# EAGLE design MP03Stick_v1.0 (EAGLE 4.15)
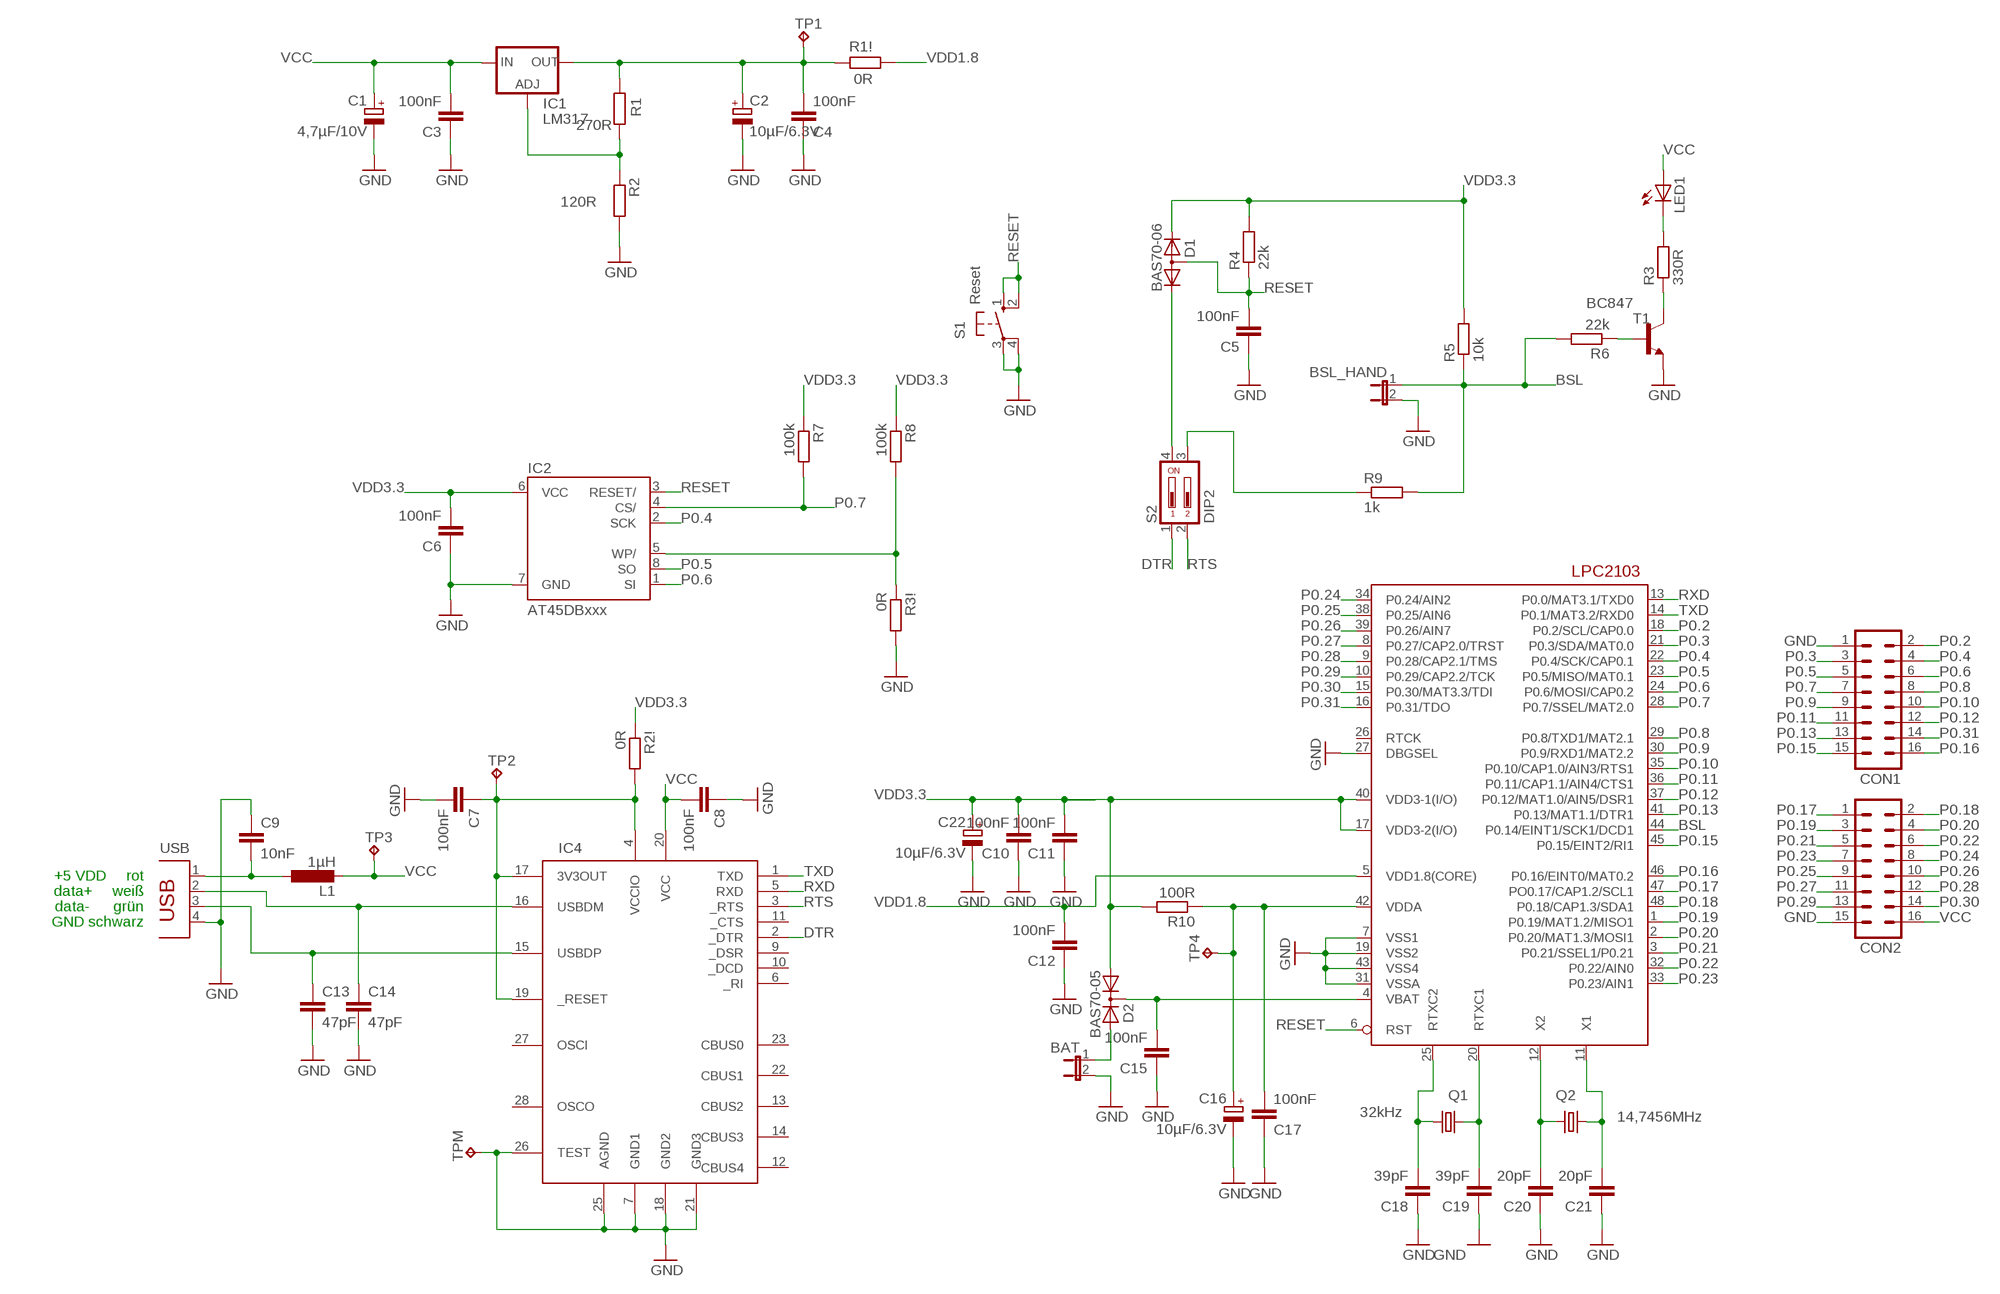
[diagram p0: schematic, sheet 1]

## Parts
BAT  JP1EMP  [JP1_MP]
BSL_HAND  JP1EMP  [JP1_MP]
C1  4,7µF/10V  CPOL-EUA/3216-18R  [A/3216-18R]
C2  10µF/6.3V  CPOL-EUA/3216-18R  [A/3216-18R]
C3  100nF  C-EUC0805K  [C0805K]
C4  100nF  C-EUC0805K  [C0805K]
C5  100nF  C-EUC0805K  [C0805K]
C6  100nF  C-EUC0805K  [C0805K]
C7  100nF  C-EUC0805K  [C0805K]
C8  100nF  C-EUC0805K  [C0805K]
C9  10nF  C-EUC0805K  [C0805K]
C10  100nF  C-EUC0805K  [C0805K]
C11  100nF  C-EUC0805K  [C0805K]
C12  100nF  C-EUC0805K  [C0805K]
C13  47pF  C-EUC0805K  [C0805K]
C14  47pF  C-EUC0805K  [C0805K]
C15  100nF  C-EUC0805K  [C0805K]
C16  10µF/6.3V  CPOL-EUA/3216-18R  [A/3216-18R]
C17  100nF  C-EUC0805K  [C0805K]
C18  39pF  C-EUC0805K  [C0805K]
C19  39pF  C-EUC0805K  [C0805K]
C20  20pF  C-EUC0805K  [C0805K]
C21  20pF  C-EUC0805K  [C0805K]
C22  10µF/6.3V  CPOL-EUA/3216-18R  [A/3216-18R]
CON1  ML16  [ML16]
CON2  ML16  [ML16]
D1  BAS70-06  [SOT23]
D2  BAS70-05  [SOT23]
IC1  LM317  LM317LSO8  [SO08]
IC2  AT45DBxxx  AT45DB  [SOIC8]
IC3  LPC2103  [LQFP48]
IC4  FT232RL  [SSOP28DB]
L1  1µH  L-EUL2825P  [L2825P]
LED1  LED3MM  [LED3MM]
Q1  32kHz  CRYTALTC26H  [TC26H]
Q2  14,7456MHz  CRYTALHC49U-V  [HC49U-V]
R1  270R  R-EU_R0805  [R0805]
R1!  0R  R-EU_R0805  [R0805]
R2  120R  R-EU_R0805  [R0805]
R2!  0R  R-EU_R0805  [R0805]
R3  330R  R-EU_R0805  [R0805]
R3!  0R  R-EU_R0805  [R0805]
R4  22k  R-EU_R0805  [R0805]
R5  10k  R-EU_R0805  [R0805]
R6  22k  R-EU_R0805  [R0805]
R7  100k  R-EU_R0805  [R0805]
R8  100k  R-EU_R0805  [R0805]
R9  1k  R-EU_R0805  [R0805]
R10  100R  R-EU_R0805  [R0805]
S1  Reset  10-XX  [B3F-10XX]
S2  DIP2  DS02  [DS-02]
T1  BC847  BC847-NPN-SOT23-BEC  [SOT23-BEC]
TP1  TP09SQ  [TP09SQ]
TP2  TP09SQ  [TP09SQ]
TP3  TP09SQ  [TP09SQ]
TP4  TP09SQ  [TP09SQ]
TPM  TP09SQ  [TP09SQ]
USB  PN61729  [PN61729]

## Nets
BSL: BSL_HAND.1 IC3.44(P0.14/EINT1/SCK1/DCD1) R5.1 R6.2 R9.2
DTR: IC4.2(_DTR) S2.1
GND: BAT.2 BSL_HAND.2 C1.- C2.- C3.1 C4.1 C5.1 C6.1 C7.2 C8.1 C9.1 C10.1 C11.1 C12.1 C13.2 C14.2 C15.1 C16.- C17.1 C18.1 C19.1 C20.1 C21.1 C22.- CON1.1 CON2.15 IC2.7(GND) IC3.7(VSS1) IC3.19(VSS2) IC3.27(DBGSEL) IC3.31(VSSA) IC3.43(VSS4) IC4.7(GND1) IC4.18(GND2) IC4.21(GND3) IC4.25(AGND) IC4.26(TEST) R2.2 R3!.2 S1.3(P) S1.4(P1) T1.E TPM.TP USB.4
N$1: C9.2 L1.1 USB.1
N$2: R6.1 T1.B
N$3: R9.1 S2.3
N$4: C14.1 IC4.16(USBDM) USB.2
N$5: R3.1 T1.C
N$6: LED1.K(C) R3.2
N$7: C13.1 IC4.15(USBDP) USB.3
N$8: D1.1(K1) S2.4
N$9: IC1.4(ADJ) R1.1 R2.1
N$10: BAT.1 D2.2(A2)
N$13: C19.2 IC3.20(RTXC1) Q1.2
N$14: C20.2 IC3.12(X2) Q2.2
N$15: C21.2 IC3.11(X1) Q2.1
N$16: C18.2 IC3.25(RTXC2) Q1.1
P0.2: CON1.2 IC3.18(P0.2/SCL/CAP0.0)
P0.3: CON1.3 IC3.21(P0.3/SDA/MAT0.0)
P0.4: CON1.4 IC2.2(SCK) IC3.22(P0.4/SCK/CAP0.1)
P0.5: CON1.5 IC2.8(SO) IC3.23(P0.5/MISO/MAT0.1)
P0.6: CON1.6 IC2.1(SI) IC3.24(P0.6/MOSI/CAP0.2)
P0.7: CON1.7 IC2.4(CS/) IC3.28(P0.7/SSEL/MAT2.0) R7.2
P0.8: CON1.8 IC3.29(P0.8/TXD1/MAT2.1)
P0.9: CON1.9 IC3.30(P0.9/RXD1/MAT2.2)
P0.10: CON1.10 IC3.35(P0.10/CAP1.0/AIN3/RTS1)
P0.11: CON1.11 IC3.36(P0.11/CAP1.1/AIN4/CTS1)
P0.12: CON1.12 IC3.37(P0.12/MAT1.0/AIN5/DSR1)
P0.13: CON1.13 IC3.41(P0.13/MAT1.1/DTR1)
P0.15: CON1.15 IC3.45(P0.15/EINT2/RI1)
P0.16: CON1.16 IC3.46(P0.16/EINT0/MAT0.2)
P0.17: CON2.1 IC3.47(PO0.17/CAP1.2/SCL1)
P0.18: CON2.2 IC3.48(P0.18/CAP1.3/SDA1)
P0.19: CON2.3 IC3.1(P0.19/MAT1.2/MISO1)
P0.20: CON2.4 IC3.2(P0.20/MAT1.3/MOSI1)
P0.21: CON2.5 IC3.3(P0.21/SSEL1/P0.21)
P0.22: CON2.6 IC3.32(P0.22/AIN0)
P0.23: CON2.7 IC3.33(P0.23/AIN1)
P0.24: CON2.8 IC3.34(P0.24/AIN2)
P0.25: CON2.9 IC3.38(P0.25/AIN6)
P0.26: CON2.10 IC3.39(P0.26/AIN7)
P0.27: CON2.11 IC3.8(P0.27/CAP2.0/TRST)
P0.28: CON2.12 IC3.9(P0.28/CAP2.1/TMS)
P0.29: CON2.13 IC3.10(P0.29/CAP2.2/TCK)
P0.30: CON2.14 IC3.15(P0.30/MAT3.3/TDI)
P0.31: CON1.14 IC3.16(P0.31/TDO)
RESET: C5.2 D1.3(A) IC2.3(RESET/) IC3.6(RST) R4.1 S1.1(S) S1.2(S1)
RTS: IC4.3(_RTS) S2.2
RXD: IC3.13(P0.0/MAT3.1/TXD0) IC4.5(RXD)
TXD: IC3.14(P0.1/MAT3.2/RXD0) IC4.1(TXD)
VBAT: C15.2 D2.3(C) IC3.4(VBAT)
VCC: C1.+ C3.2 C8.2 CON2.16 IC1.1(IN) IC4.20(VCC) L1.2 LED1.A TP3.TP
VDD1.8: C12.2 IC3.5(VDD1.8(CORE)) R1!.1
VDD1.8_OUT: C2.+ C4.2 IC1.7(OUT) R1!.2 R1.2 TP1.TP
VDD3.3: C6.2 C10.2 C11.2 C22.+ D1.2(K2) D2.1(A1) IC2.6(VCC) IC3.17(VDD3-2(I/O)) IC3.40(VDD3-1(I/O)) R2!.1 R4.2 R5.2 R7.1 R8.1 R10.2
VDDA: C16.+ C17.2 IC3.42(VDDA) R10.1 TP4.TP
VDDIO: C7.1 IC4.4(VCCIO) IC4.17(3V3OUT) IC4.19(_RESET) R2!.2 TP2.TP
WP/: IC2.5(WP/) R3!.1 R8.2
Unconnected: IC3.26(RTCK) IC4.6(_RI) IC4.9(_DSR) IC4.10(_DCD) IC4.11(_CTS) IC4.12(CBUS4) IC4.13(CBUS2) IC4.14(CBUS3) IC4.22(CBUS1) IC4.23(CBUS0) IC4.27(OSCI) IC4.28(OSCO)

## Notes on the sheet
- +5 VDD     rot
- data+     weiß
- data-      grün
- GND schwarz

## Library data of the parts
BAT BSL_HAND = jumper:JP1E: JUMPER
C1 C2 C16 C22 = rcl:CPOL-EU: POLARIZED CAPACITOR, European symbol
C3-C15 C17-C21 = rcl:C-EU: CAPACITOR, European symbol
CON1 CON2 = con-harting-ml:ML16: HARTING
D1 = diode_Mario:BAS70-06: Silicon Schottky Diodes General-purpose diode for high-speed switching
D2 = diode:BAS70-05: Silicon Schottky Diodes General-purpose diode for high-speed switching
IC1 = v-reg_Mario:LM317L: VOLTAGE REGULATOR
IC2 = atmel:AT45DB*
IC3 = philips-4:LPC2103: LPC2101/2102/2103 microcontroler from Philips
IC4 = ftdichip:FT232RL: USB UART 4th Generation USB UART (USB <-> Serial) Controller
L1 = rcl:L-EU: INDUCTOR, European symbol
LED1 = led:LED: LED
Q1 Q2 = crystal:CRYTAL: CRYSTAL
R1 R1! R2 R2! R3 R3! R4-R10 = rcl:R-EU_: RESISTOR, European symbol
S1 = switch-omron:10-XX: OMRON SWITCH
S2 = switch-dil:DS02: DIL/CODE SWITCH
T1 = transistor:*-NPN-: NPN Transistror
TP1-TP4 TPM = testpad:TP09SQ: TEST PIN
USB = con-berg:PN61729: BERG USB connector

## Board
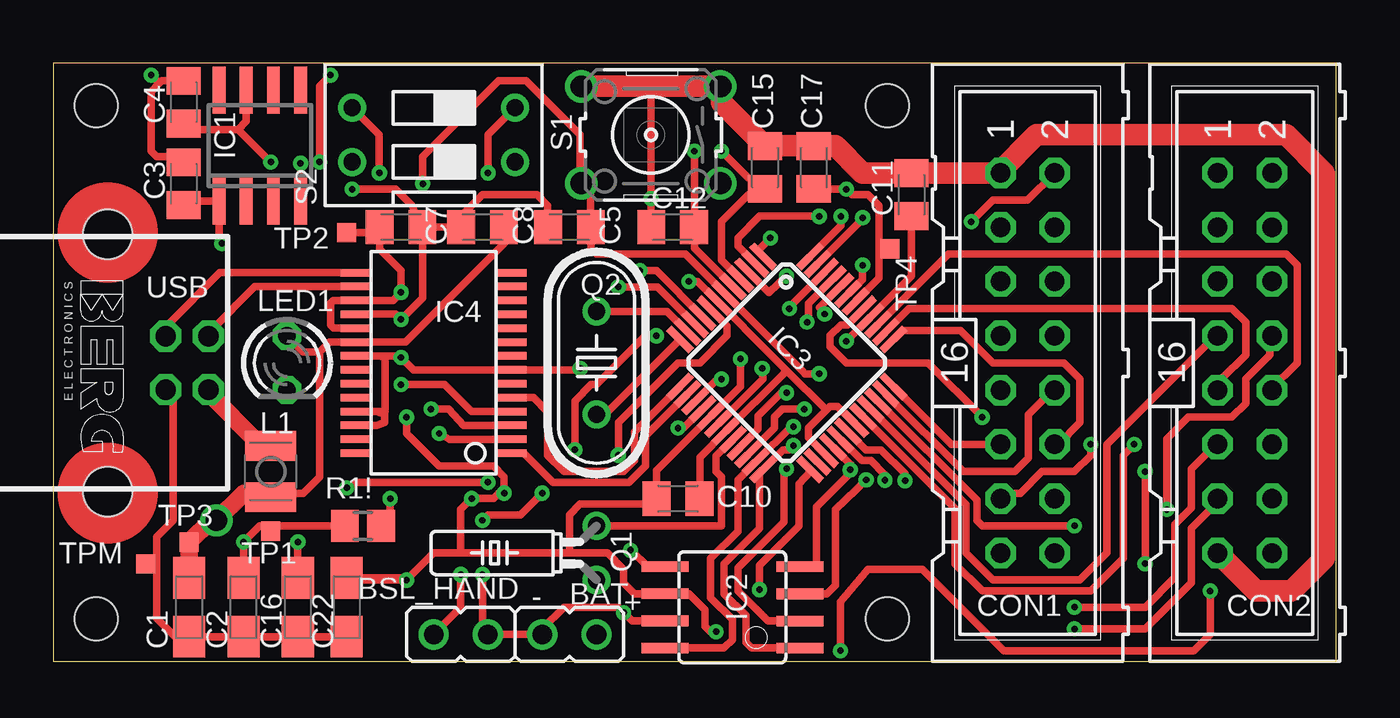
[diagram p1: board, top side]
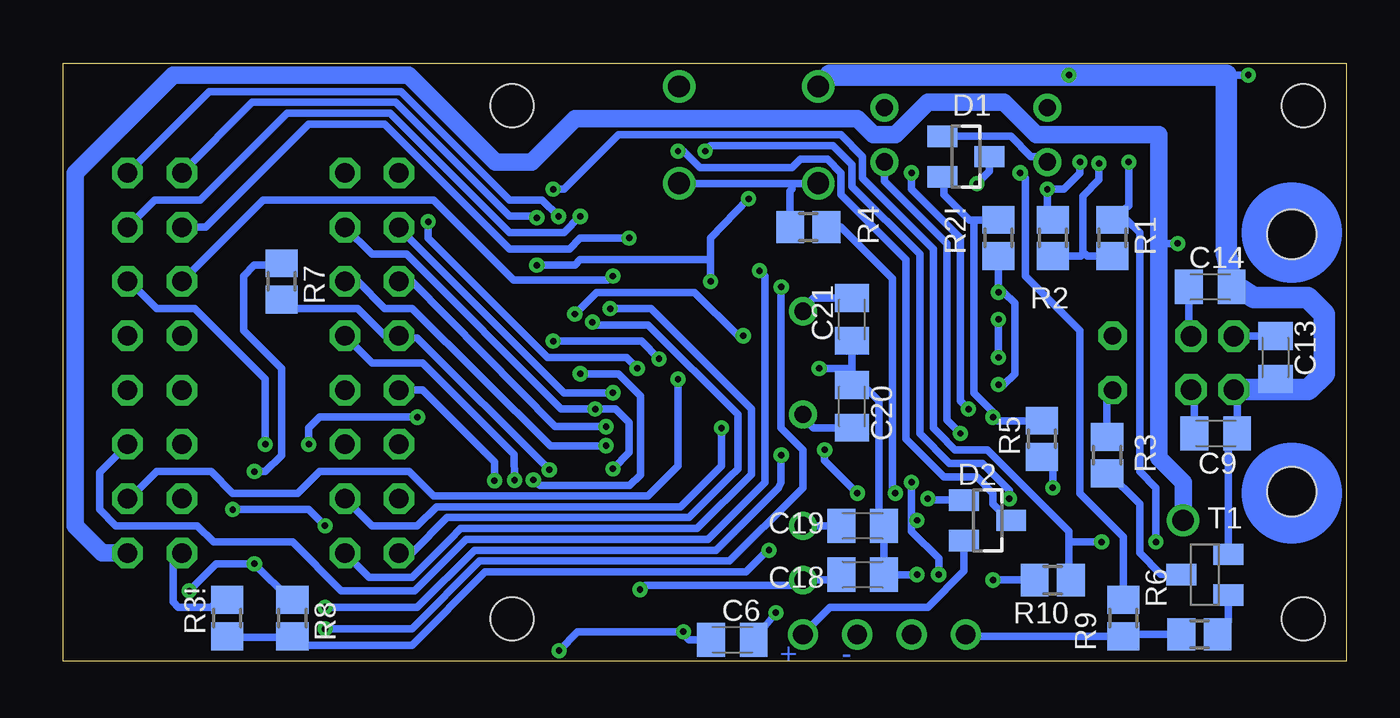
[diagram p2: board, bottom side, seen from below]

Size 60 x 28 mm. Coordinates in mm from the lower left corner, seen from the top.
Outline: 0,0 60,0 60,28 0,28 0,0
Copper layers (1+16): Top 0.035mm / dielectric 1.5mm / Bottom 0.035mm
Design rules "default": minimum track width 8mil, minimum drill 8mil, track to track 5mil, track to pad 5mil, pad to pad 5mil, via to via 5mil, smd to smd 5mil, copper to edge 8mil, drill to drill 8mil, minimum pad ring 10mil, minimum via ring 8mil, stop-mask expansion 4mil, vias tented up to drill 0mil, thermal gap 10mil
Holes 2 mm at 2,26 39,26 2,2 39,2
tRestrict: area 37,24 to 41,28; area 37,0 to 41,4; area 0,24 to 4,28; area 0,0 to 4,4
bRestrict: area 0,0 to 4,4; area 0,24 to 4,28; area 37,24 to 41,28; area 37,0 to 41,4

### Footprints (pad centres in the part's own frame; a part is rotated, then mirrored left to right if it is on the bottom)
JP1_MP = drill 0.914 round: 1 0,-1.27; 2 0,1.27
A/3216-18R = smd 1.95 x 1.5: + 1.375,0; - -1.375,0
C0805K = smd 1.3 x 1.6: 1 -1,0; 2 1,0
ML16 = drill 0.914 octagon: 1 -8.89,-1.27; 2 -8.89,1.27; 3 -6.35,-1.27; 4 -6.35,1.27; 5 -3.81,-1.27; 6 -3.81,1.27; 7 -1.27,-1.27; 8 -1.27,1.27; 9 1.27,-1.27; 10 1.27,1.27; 11 3.81,-1.27; 12 3.81,1.27; 13 6.35,-1.27; 14 6.35,1.27; 15 8.89,-1.27; 16 8.89,1.27
SOT23 = smd 1 x 1.4: 1 -0.95,-1.1; 2 0.95,-1.1; 3 0,1.1
SO08 = smd 0.6 x 2.2: 1 -1.905,-2.6; 2 -0.635,-2.6; 3 0.635,-2.6; 4 1.905,-2.6; 5 1.905,2.6; 6 0.635,2.6; 7 -0.635,2.6; 8 -1.905,2.6
SOIC8 = smd 0.5 x 2.2: 1 -1.905,-3.154; 2 -0.645,-3.154; 3 0.625,-3.154; 4 1.895,-3.154; 5 1.905,3.154; 6 0.635,3.154; 7 -0.635,3.154; 8 -1.905,3.154
LQFP48 = smd 1.5 x 0.35: 1 -4.3,2.75; 2 -4.3,2.25; 3 -4.3,1.75; 4 -4.3,1.25; 5 -4.3,0.75; 6 -4.3,0.25; 7 -4.3,-0.25; 8 -4.3,-0.75; 9 -4.3,-1.25; 10 -4.3,-1.75; 11 -4.3,-2.25; 12 -4.3,-2.75; 25 4.3,-2.75; 26 4.3,-2.25; 27 4.3,-1.75; 28 4.3,-1.25; 29 4.3,-0.75; 30 4.3,-0.25; 31 4.3,0.25; 32 4.3,0.75; 33 4.3,1.25; 34 4.3,1.75; 35 4.3,2.25; 36 4.3,2.75 | smd 0.35 x 1.5: 13 -2.75,-4.3; 14 -2.25,-4.3; 15 -1.75,-4.3; 16 -1.25,-4.3; 17 -0.75,-4.3; 18 -0.25,-4.3; 19 0.25,-4.3; 20 0.75,-4.3; 21 1.25,-4.3; 22 1.75,-4.3; 23 2.25,-4.3; 24 2.75,-4.3; 37 2.75,4.3; 38 2.25,4.3; 39 1.75,4.3; 40 1.25,4.3; 41 0.75,4.3; 42 0.25,4.3; 43 -0.25,4.3; 44 -0.75,4.3; 45 -1.25,4.3; 46 -1.75,4.3; 47 -2.25,4.3; 48 -2.75,4.3
SSOP28DB = smd 0.348 x 1.397: 1 -4.225,-3.656; 2 -3.575,-3.656; 3 -2.925,-3.656; 4 -2.275,-3.656; 5 -1.625,-3.656; 6 -0.975,-3.656; 7 -0.325,-3.656; 8 0.325,-3.656; 9 0.975,-3.656; 10 1.625,-3.656; 11 2.275,-3.656; 12 2.925,-3.656; 13 3.575,-3.656; 14 4.225,-3.656; 15 4.225,3.656; 16 3.575,3.656; 17 2.925,3.656; 18 2.275,3.656; 19 1.625,3.656; 20 0.975,3.656; 21 0.325,3.656; 22 -0.325,3.656; 23 -0.975,3.656; 24 -1.625,3.656; 25 -2.275,3.656; 26 -2.925,3.656; 27 -3.575,3.656; 28 -4.225,3.656
L2825P = smd 1.4 x 2.4: 1 -1.2,0; 2 1.2,0
LED3MM = drill 0.813 octagon: A -1.27,0; K 1.27,0
TC26H = drill 0.813 round: 1 -1.27,0; 2 1.27,0
HC49U-V = drill 0.813 round: 1 -2.413,0; 2 2.413,0
R0805 = smd 1.3 x 1.5: 1 -0.85,0; 2 0.85,0
B3F-10XX = drill 1.016 round: 1 -3.251,2.261; 2 3.251,2.261; 3 -3.251,-2.261; 4 3.251,-2.261
DS-02 = drill 0.813 round: 1 -1.27,-3.81; 2 1.27,-3.81; 3 1.27,3.81; 4 -1.27,3.81
SOT23-BEC = smd 1 x 1.4: B -0.95,-1.1; C 0,1.1; E 0.95,-1.1
TP09SQ = smd 0.9 x 0.9: TP 0,0
PN61729 = drill 0.95 octagon: 1 1.25,4.71; 2 -1.25,4.71; 3 -1.25,2.71; 4 1.25,2.71 | hole 2.3: -6.02,0; 6.02,0

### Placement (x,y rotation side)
BAT  24.13,1.27 90 top
BSL_HAND  19.05,1.27 270 top
C1  6.35,2.54 90 top
C2  8.89,2.54 90 top
C3  6.1,22.35 270 top
C4  6.1,26.16 270 top
C5  24.13,20.32 0 top
C6  28.7,1.02 180 bottom
C7  16.26,20.32 0 top
C8  20.07,20.32 0 top
C9  6.1,10.67 180 bottom
C10  29.21,7.62 180 top
C11  40.13,21.84 270 top
C12  28.96,20.32 0 top
C13  3.3,14.22 270 bottom
C14  6.35,17.53 0 bottom
C15  33.27,23.11 270 top
C16  11.43,2.54 90 top
C17  35.56,23.11 270 top
C18  22.61,4.06 180 bottom
C19  22.61,6.35 180 bottom
C20  23.11,11.94 270 bottom
C21  23.11,16 90 bottom
C22  13.72,2.54 90 top
CON1  45.56,13.97 270 top
CON2  55.72,13.97 270 top
D1  17.78,23.62 270 bottom
D2  16.76,6.6 270 bottom
IC1  9.65,24.13 0 top
IC2  31.75,2.54 90 top
IC3  34.29,13.97 315 top
IC4  17.78,13.97 90 top
L1  10.16,8.89 270 top
LED1  10.92,13.97 270 top
Q1  25.4,5.08 90 top
Q2  25.4,13.97 270 top
R1  10.92,19.81 90 bottom
R1!  14.48,6.35 180 top
R2  13.72,19.81 90 bottom
R2!  16.26,19.81 270 bottom
R3  11.18,9.65 90 bottom
R3!  52.32,2.03 90 bottom
R4  25.15,20.32 0 bottom
R5  14.22,10.41 90 bottom
R6  6.86,1.27 180 bottom
R7  49.78,17.78 270 bottom
R8  49.28,2.03 270 bottom
R9  10.41,2.03 270 bottom
R10  13.72,3.81 180 bottom
S1  27.94,24.64 180 top
S2  17.78,24.64 90 top
T1  6.6,4.06 90 bottom
TP1  10.16,6.1 0 top
TP2  13.72,20.07 0 top
TP3  6.35,5.59 0 top
TP4  39.12,19.3 0 top
TPM  4.32,4.57 0 top
USB  2.54,13.97 270 top

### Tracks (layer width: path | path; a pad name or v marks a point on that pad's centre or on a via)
BSL  (via drill 0.3)
  Top 0.356: IC3.44 35.81,16.55 v36.07,16.26 | v19.05,4.06 19.05,2.54 BSL_HAND.1 | v20.32,8.38 14.22,8.38 v13.72,8.13 | v28.19,15.24 27.69,15.24 25.4,12.95 25.15,12.95 24.38,12.19 v24.38,9.91 | v22.86,7.87 21.84,6.86 20.32,6.86 v20.07,6.6
  Bottom 0.356: v36.07,16.26 35.05,17.27 30.99,17.27 30.48,17.27 28.45,15.24 v28.19,15.24 | R6.2 10.41,1.27 R9.2 17.61,1.18 BSL_HAND.1 | R5.1 14.39,9.56 13.72,9.4 v13.72,8.13 | v20.32,8.38 20.32,8.13 20.32,6.6 | 20.32,6.6 20.32,6.1 19.05,4.83 19.05,4.32 v19.05,4.06 | v24.38,9.91 24.38,9.4 v22.86,7.87 | 20.32,6.6 v20.07,6.6
DTR  (via drill 0.3)
  Top 0.356: IC4.2 18.52,10.39 v18.03,10.67
  Bottom 0.356: S2.1 21.59,22.48 18.67,19.56 18.67,11.3 v18.03,10.67
GND  (via drill 0.3)
  Top 0.356: 27.94,19.97 27.94,20.32 C12.1 27.94,20.34 27.94,21.59 v27.94,21.65 27.94,26.67 27.94,26.92 | C10.1 30.23,7.62 30.23,9.55 IC3.19 34.14,13.46 34.16,13.49 34.26,13.59 34.29,13.59 | 39.78,22.76 39.88,22.86 40.12,22.86 C11.1 | IC3.43 37.85,17.88 v37.85,18.54 | IC3.31 36.67,11.94 36.58,11.94 36.32,11.94 36.2,11.81 | IC3.27 35.31,10.48 35.31,10.92 36.2,11.81 | IC2.7 27.05,1.91 v26.67,2.29 26.42,2.54 23.88,2.54 22.86,1.52 BAT.2 BSL_HAND.2 20.07,1.52 v20.07,4.06 | 34.3,13.6 36.09,11.81 36.2,11.81 | 34.3,13.6 33.66,14.25 33.54,14.37 IC3.7 30.13,17.78 v29.72,17.78 | 34.29,13.59 | 34.3,13.6 34.29,13.59 | 4.83,4.57 4.83,2.03 5.69,1.17 C1.- 8.79,1.17 8.89,1.27 C2.- 11.32,1.17 11.43,1.27 C16.- 11.58,1.17 11.68,1.27 11.79,1.17 C22.- | 4.83,4.57 4.83,5.84 5.59,6.6 5.59,12.45 5.33,12.7 5.31,12.72 USB.4 | 24.64,13.64 16.84,13.64 16.76,13.72 | 24.64,13.64 IC4.7 | 15.24,14.29 IC4.21 | 15.24,14.29 16.18,14.29 v16.26,14.22 | IC4.26 15.11,11.04 15.49,11.18 15.49,11.56 15.1,11.7 | 15.1,11.7 IC4.25 15.1,11.7 | 15.1,11.7 15.51,11.7 15.51,14.21 15.49,14.22 15.24,14.29 | IC4.18 16.01,16.25 v16.26,16 17.26,17 C7.2 | 16.76,13.72 v16.26,14.22 | v24.64,13.72 24.64,13.64 | C4.1 5.06,27.16 4.95,27.05 | 4.95,27.05 4.57,26.67 4.57,23.88 4.83,23.62 5.59,23.62 5.84,23.37 5.86,23.35 C3.1 | 4.95,27.05 4.83,27.18 v4.57,27.43 | v12.45,23.37 12.45,26.92 v12.95,27.43 | C7.2 19.05,20.32 C8.1 19.07,20.84 20.07,21.84 22.61,21.84 23.11,21.34 23.11,20.32 C5.1 | C7.2 16.75,21.35 16,22.1 v13.97,22.1 | 4.83,4.57 TPM.TP | 16.76,13.72 v16.26,14.22
  Top 1.016: C17.1 33.27,24.13 36.58,24.13 37.85,22.86 38.86,22.86 39.88,22.86 44.2,22.86 45.97,24.64 57.66,24.64 59.44,22.86 59.44,4.83 57.91,3.3 56.23,3.3 CON2.15 | C15.1 31.24,26.15 31.24,26.92 | 24.64,26.92 27.94,26.92 31.17,26.92
  Top 1.27: C15.1 33.27,24.13 | 31.24,26.92 31.22,26.92 S1.3 31.17,26.92 | 24.64,26.92 24.66,26.92 S1.4 | 44.2,22.86 CON1.1 44.2,22.86
  Bottom 0.356: v37.85,18.54 36.07,18.54 35.81,18.8 33.02,18.8 29.72,18.8 | 23.11,13.72 23.11,14.99 C21.1 | 23.11,13.72 23.11,13.46 C20.1 23.11,12.7 22.35,12.7 21.84,12.19 21.84,6.6 21.61,6.37 C19.1 21.61,4.08 21.59,4.06 C18.1 v20.07,4.06 | C6.1 27.69,1.02 v26.67,2.29 | R3!.2 52.74,2.88 53.09,2.54 54.61,2.54 54.86,2.79 54.86,4.83 54.61,5.08 CON2.15 | 29.72,18.8 29.72,18.54 v29.72,17.78 | v27.94,21.65 29.72,19.81 29.72,18.8 | 23.11,13.72 v24.64,13.72 | 5.59,27.43 v4.57,27.43 | 13.97,21.08 13.72,20.83 | 13.72,20.83 R2.2 13.72,20.83 | v13.97,22.1 13.97,21.08 | v13.97,22.1 13.21,22.1 12.45,22.86 v12.45,23.37 | USB.4 5.31,12.72 5.33,12.7 5.1,12.46 C9.1 5.08,10.67 5.5,10.24 T1.E | 5.49,17.78 C14.2 | 3.3,12.72 3.3,12.7 C13.2 | v13.97,22.1 13.97,21.34 13.97,21.08 | 13.97,21.08 13.72,20.83 | v16.26,14.22 v16.26,16
  Bottom 1.016: USB.4 3.3,12.72 1.76,12.72 1.02,13.46 1.02,16.26 1.78,17.02 4.32,17.02 5.49,17.78 5.49,18.54 5.59,19.05 5.59,27.43 v12.95,27.43 24.13,27.43 24.64,26.92 | 24.66,26.9 S1.4
  Bottom 1.27: 24.64,26.92 24.66,26.9
N$1
  Top 0.813: USB.1 7.13,12.72 7.11,12.7 9.72,10.09 L1.1
  Bottom 0.356: USB.1 7.35,12.72 7.37,12.7 7.1,12.43 C9.2
N$2
  Bottom 0.356: R6.1 6.01,1.36 5.84,1.52 5.5,1.86 T1.B
N$3  (via drill 0.3)
  Top 0.356: v15.24,22.86 15.24,24.64 S2.3
  Bottom 0.356: R9.1 10.41,5.84 12.45,7.87 12.45,15.49 14.99,18.03 14.99,21.34 14.99,22.61 v15.24,22.86
N$4
  Top 0.356: USB.2 7.25,15.38 7.37,15.49 9.42,17.55 IC4.16
  Bottom 0.356: USB.2 7.35,15.22 7.37,15.24 7.35,15.26 C14.1
N$5
  Bottom 0.356: T1.C 8.66,4.08 9.65,5.08 9.65,7.37 11.18,8.89 R3.1
N$6
  Bottom 0.356: R3.2 11.18,12.45 LED1.K
N$7
  Top 0.356: IC4.15 7.78,18.2 5.33,15.75 5.33,15.24 5.31,15.22 USB.3
  Bottom 0.356: USB.3 5.1,15.22 5.08,15.24 5.06,15.22 C13.1
N$8
  Bottom 0.356: D1.1 15.68,24.57 14.73,23.62 14.22,23.62 S2.4
N$9  (via drill 0.3)
  Top 0.356: IC1.4 11.56,21.72 11.68,21.84 11.56,22.48 v11.56,23.3
  Bottom 0.356: R2.1 12.41,18.96 12.32,19.05 | 12.32,19.05 12.32,21.78 11.56,22.54 v11.56,23.3 | 12.32,19.05 12.19,19.05 12.1,18.96 R1.1
N$10
  Bottom 0.356: D2.2 17.86,4.23 19.56,2.54 24.13,2.54 BAT.1
N$13
  Top 0.356: Q1.2 31.24,6.35 31.24,6.86 31.24,8.64 30.99,8.89 30.99,9.61 IC3.20
  Bottom 0.356: C19.2 Q1.2
N$14
  Top 0.356: Q2.2 25.4,11.68 25.92,11.68 IC3.12
  Bottom 0.356: Q2.2 25.4,11.43 24.91,10.94 C20.2
N$15
  Top 0.356: IC3.11 28.7,16.38 Q2.1
  Bottom 0.356: Q2.1 25.4,16.51 24.91,17 C21.2
N$16  (via drill 0.3)
  Top 0.356: v33.02,3.37 33.01,3.38 33.02,3.43 33.02,4.51 34.86,6.35 34.86,8.32 35.43,8.9 IC3.25
  Bottom 0.356: C18.2 23.86,3.81 25.15,3.81 Q1.1 25.65,3.56 32.77,3.56 v33.02,3.37
P0.2  (via drill 0.3)
  Top 0.356: CON1.2 45.56,21.59 43.94,21.59 v42.93,20.57 | IC3.18 33.17,13.21 v33.15,13.72
  Bottom 0.356: v42.93,20.57 42.93,19.81 37.34,14.22 37.08,14.22 33.66,14.22 v33.15,13.72
P0.3  (via drill 0.3)
  Top 0.356: IC3.21 32.96,10.87 32.96,11.24 32.95,11.49 34.04,12.57 v34.29,12.57
  Bottom 0.356: CON1.3 44.07,20.07 36.58,12.57 34.42,12.57 v34.29,12.57
P0.4  (via drill 0.3)
  Top 0.356: IC3.22 33.72,10.92 33.72,11.43 34.1,11.81 v35.12,11.81 | IC2.2 33.41,1.9 32,3.3 32,4.38 34.16,6.54 34.16,8.76 v34.29,9.02
  Bottom 0.356: CON1.4 45.56,19.05 43.94,19.05 36.7,11.81 | v35.12,11.81 36.7,11.81 | v35.12,11.81 36.7,11.81 | v35.12,11.81 34.92,11.81 34.16,11.81 33.53,11.18 33.53,9.78 v34.29,9.02
P0.5  (via drill 0.3)
  Top 0.356: v34.61,10.99 34.67,11.05 34.55,11.05 IC3.23 32,8.5 32,6.1 30.73,4.83 30.73,2.98 31.75,1.97 31.75,1.02 31.37,0.64 IC2.8
  Bottom 0.356: CON1.5 43.69,17.78 36.99,10.99 v34.61,10.99
P0.6  (via drill 0.3)
  Top 0.356: IC2.1 32.64,0.64 32.38,0.89 32.38,2.16 31.37,3.17 31.37,4.57 33.02,6.22 33.02,8.81 IC3.24 34.12,9.91 34.29,9.91 34.42,9.91 v34.61,10.1
  Bottom 0.356: CON1.6 46.2,17.78 44.96,16.51 43.69,16.51 37.21,10.1 36.32,10.1 v34.61,10.1
P0.7  (via drill 0.3)
  Top 0.356: IC3.28 37.34,9.15 37.34,8.89 | IC2.4 35.68,4.43 35.69,7.24 37.34,8.89 | 37.34,8.89 v37.26,8.97 37.34,8.89
  Bottom 0.356: v37.26,8.97 43.43,15.15 CON1.7 44.96,15.24 46.23,16.51 49.53,16.51 49.78,16.76 R7.2
P0.8  (via drill 0.3)
  Top 0.356: IC3.29 37.8,9.4 38.23,9.4 38.86,8.76 v38.89,8.48
  Bottom 0.356: CON1.8 45.56,13.97 43.18,13.97 38.9,9.69 v38.89,8.48
P0.9  (via drill 0.3)
  Top 0.356: v39.83,8.46 39.81,8.79 38.7,9.91 38.04,9.91 38,9.91 IC3.30
  Bottom 0.356: v39.83,8.46 39.83,9.35 43.18,12.7 44.2,12.7 CON1.9
P0.10
  Top 0.356: IC3.35 42.55,8.89 44.96,8.89 45.59,9.53 45.59,11.56 46.74,12.7 CON1.10
P0.11
  Top 0.356: CON1.11 44.2,10.16 41.99,10.16 IC3.36
P0.12
  Top 0.356: IC3.37 39.7,15.49 42.42,15.49 43.94,13.97 47.24,13.97 48.01,13.21 48.01,11.18 46.99,10.16 CON1.12
P0.13  (via drill 0.3)
  Top 0.356: IC3.41 37.13,15.75 36.83,15.75 36.32,15.24 36.32,14.73 37.08,13.97 40.89,13.97 v43.43,11.43 | 44.39,7.68 44.58,7.87 45.21,7.87 46.23,8.89 47.75,8.89 48.51,9.65 v48.51,10.16 | 44.39,7.68 44.32,7.62 | 44.39,7.68 44.45,7.62 CON1.13
  Bottom 0.356: v48.51,10.16 48.51,10.92 48.01,11.43 v43.43,11.43
P0.15  (via drill 0.3)
  Top 0.356: v35.24,15.88 35.31,15.94 35.31,16 35.31,16.75 IC3.45
  Bottom 0.356: CON1.15 43.69,5.08 42.04,6.73 30.73,6.73 28.83,8.64 28.45,9.02 28.45,11.56 32.64,15.75 35.05,15.75 v35.24,15.88
P0.16  (via drill 0.3)
  Top 0.356: v34.42,16.51 34.35,16.51 | 34.35,16.51 34.29,16.51 34.35,16.51 | 34.35,16.51 IC3.46
  Bottom 0.356: CON1.16 45.69,3.94 43.69,3.94 41.91,5.71 | 41.4,6.22 41.91,5.71 | 30.35,6.22 31.24,6.22 | 30.35,6.22 31.24,6.22 | 31.24,6.22 41.4,6.22 | 41.4,6.22 41.91,5.71 | 41.4,6.22 41.91,5.71 | 30.35,6.22 27.81,8.76 27.81,11.81 32.51,16.51 v34.42,16.51 | 30.35,6.22 31.24,6.22
P0.17  (via drill 0.3)
  Top 0.356: IC3.47 37.71,20.57 v37.85,20.77
  Bottom 0.356: CON2.1 51.15,26.16 44.45,26.16 39.12,20.83 37.91,20.83 v37.85,20.77
P0.18  (via drill 0.3)
  Top 0.356: IC3.48 36.83,20.4 v36.83,20.83
  Bottom 0.356: CON2.2 53.18,26.67 44.2,26.67 39.12,21.59 37.59,21.59 v36.83,20.83
P0.19  (via drill 0.3)
  Top 0.356: IC3.1 33.02,19.13 33.02,19.3 v33.53,19.81
  Bottom 0.356: CON2.3 53.34,20.32 48.51,25.15 44.96,25.15 39.12,19.3 36.32,19.3 35.81,19.81 v33.53,19.81
P0.20  (via drill 0.3)
  Top 0.356: IC3.2 32,19.44 32,19.81 33.02,20.83 v35.81,20.83
  Bottom 0.356: CON2.4 55.72,21.59 53.59,21.59 49.53,25.65 44.7,25.65 39.12,20.07 36.58,20.07 | 36.58,20.07 v35.81,20.83 36.58,20.07
P0.21  (via drill 0.3)
  Top 0.356: IC3.3 33.46,17.27 v34.29,18.03
  Bottom 0.356: 50.64,21.59 CON2.5 | 50.55,21.59 50.64,21.59 | 50.55,21.59 50.64,21.59 | 50.55,21.59 50.64,21.59 | 50.55,21.59 42.67,21.59 38.92,17.84 34.54,17.84 v34.29,18.03
P0.22  (via drill 0.3)
  Top 0.356: IC3.32 42.16,7.16 42.16,4.57 43.43,3.3 48.51,3.3 50.04,4.83 50.04,9.65 v50.55,10.16
  Bottom 0.356: v50.55,10.16 50.55,13.21 53.85,16.51 55.63,16.51 56.9,17.78 CON2.6
P0.23
  Top 0.356: IC3.33 42.67,7.36 42.67,5.08 43.94,3.81 48.01,3.81 49.28,5.08 49.28,10.16 54.36,15.24 CON2.7
P0.24  (via drill 0.3)
  Top 0.356: IC3.34 43.18,7.55 43.18,6.6 43.43,6.35 v47.75,6.35 | v52.07,7.11 52.07,10.41 53.09,11.43 55.12,11.43 55.75,12.06 55.75,13.21 56.9,14.35 56.9,15.11 56.9,15.15 CON2.8
  Bottom 0.356: v47.75,6.35 48.51,7.11 v52.07,7.11
P0.25
  Top 0.356: IC3.38 40.01,16.51 55.12,16.51 55.75,15.88 55.75,14.35 54.61,13.21 CON2.9
P0.26
  Top 0.356: IC3.39 41.84,19.05 57.66,19.05 58.17,18.54 58.17,13.97 56.9,12.7 CON2.10
P0.27  (via drill 0.3)
  Top 0.356: IC3.8 31.5,15.7 31.5,15.24 30.23,13.97 29.21,13.97 26.42,11.18 v26.42,9.65 | v47.75,2.54 51.05,2.54 52.45,3.94 52.45,6.41 53.21,7.18 53.21,9.02 54.36,10.16 CON2.11
  Bottom 0.356: v26.42,9.65 26.42,8.38 26.54,8.13 29.46,5.21 40.77,5.21 43.43,2.54 v47.75,2.54
P0.28  (via drill 0.3)
  Top 0.356: 28.2,18.29 28.71,17.78 | 28.2,18.29 28.71,17.78 | 28.2,18.29 28.71,17.78 | 28.2,18.29 IC3.9 | 28.19,18.29 | 28.19,18.29 28.2,18.29 | v27.43,18.29 28.19,18.29
  Bottom 0.356: CON2.12 58.29,8.86 58.29,7.11 57.53,6.35 53.72,6.35 52.96,5.59 49.28,5.59 46.99,3.3 43.56,3.3 41.15,5.71 29.84,5.71 27.18,8.38 27.18,18.03 v27.43,18.29
P0.29  (via drill 0.3)
  Top 0.356: IC3.10 28.26,17.53 26.67,17.53 | 26.67,17.53 v26.42,17.53 26.67,17.53 | v47.75,1.52 51.05,1.52 53.21,3.68 53.21,6.22 54.36,7.37 54.36,7.53 CON2.13
  Bottom 0.356: v47.75,1.52 43.69,1.52 40.51,4.7 28.83,4.7 25.65,7.87 25.4,8.13 25.4,9.91 26.42,10.92 v26.42,17.53
P0.30  (via drill 0.3)
  Top 0.356: IC3.15 31.05,13.21 v31.24,13.21
  Bottom 0.356: v31.24,13.21 31.24,9.14 32.64,7.75 42.67,7.75 43.81,8.89 48.01,8.89 49.02,7.87 52.07,7.87 53.09,8.89 55.63,8.89 56.9,7.62 CON2.14
P0.31  (via drill 0.3)
  Top 0.356: 29.46,10.92 v29.21,10.92 29.46,10.92 | IC3.16 29.47,10.92 29.46,10.92
  Bottom 0.356: CON1.14 45.56,6.35 43.43,6.35 42.55,7.24 31.11,7.24 | 30.99,7.37 31.11,7.24 | 30.99,7.37 29.21,9.14 v29.21,10.92 | 30.99,7.37 31.11,7.24 | 30.99,7.37 31.11,7.24
RESET  (via drill 0.3)
  Top 0.356: IC2.3 36.19,3.17 36.58,3.56 36.58,7.11 v38.01,8.5 | v35.81,13.46 35.56,13.46 35.15,13.46 35.05,13.56 IC3.6 29.56,19.05 26.92,19.05 25.4,19.05 25.15,19.3 25.15,20.32 C5.2 25.13,21.86 24.64,22.35 | 24.64,22.35 24.66,22.38 | 24.66,22.38 S1.2 24.66,22.38 | 24.64,22.35 24.66,22.38 | 24.64,22.35 24.64,22.61 24.64,24.64 22.1,27.18 20.83,27.18 19.3,25.65 17.27,23.62 v17.27,22.35
  Bottom 0.356: v38.01,8.5 37.69,8.23 33.5,8.23 32.99,8.74 32.99,12.42 34.04,13.46 v35.81,13.46 | S1.1 30.96,22.35 25.91,22.35 | 25.91,22.35 25.15,22.35 24.89,22.35 24.71,22.35 S1.2 | D1.3 16.68,22.94 v17.27,22.35 | 25.91,22.35 25.91,22.1 26,22.01 R4.1
RTS  (via drill 0.3)
  Top 0.356: S2.2 20.32,24.64 v20.32,22.86 | 18.48,11.81 v17.65,11.81 18.48,11.81 | IC4.3 19.18,11.04 18.48,11.81
  Bottom 0.356: v20.32,22.86 20.32,22.1 18.03,19.81 18.03,12.19 v17.65,11.81
RXD
  Top 0.356: IC4.5 22.45,12.35 23.11,11.68 23.11,9.65 23.88,8.89 26.67,8.89 27.18,9.4 27.18,10.41 27.18,10.75 IC3.13
TXD
  Top 0.356: IC3.14 27.69,10.55 27.69,9.14 26.92,8.38 23.37,8.38 22.1,9.65 22,9.74 IC4.1
VBAT  (via drill 0.3)
  Top 0.356: IC3.4 31.24,18.79 31.24,20.07 31.24,20.57 32.51,21.84 33.02,21.84 33.27,22.1 | C15.2 33.27,22.1 | C15.2 32.5,22.62 32.51,22.61 v31.24,23.88 | C15.2 33.27,22.1
  Bottom 0.356: v31.24,23.88 30.99,23.88 30.23,23.11 25.91,23.11 25.53,23.5 24.26,23.5 23.62,22.86 23.62,21.84 20.57,18.8 20.57,10.41 18.8,8.64 17.27,8.64 16.51,7.87 16.51,7.37 15.75,6.6 D2.3
VCC  (via drill 0.3, 1)
  Top 0.356: 12.45,14.48 12.91,14.95 IC4.20 16.47,14.95 17.02,15.49 20.57,19.05 21.07,19.54 C8.2 | 12.45,14.48 12.45,8.64 11.68,7.87 10.67,7.87 10.41,7.62 10.34,7.69 L1.2 | C3.2 6.1,21.59 6.16,21.53 IC1.1 7.75,19.68 v7.87,19.56 | 12.45,14.48 11.68,14.48 LED1.A
  Top 0.813: L1.2 10.16,7.62 9.91,7.87 8.89,7.87 v7.62,6.6 7.37,6.6 TP3.TP C1.+
  Bottom 0.356: 8.76,19.56 v7.87,19.56
  Bottom 0.813: CON2.16 58.17,5.08 59.44,6.35 59.44,22.86 54.86,27.43 43.84,27.43 39.78,23.37 38.1,23.37 36.07,25.4 22.86,25.4 22.1,24.64 21.08,24.64 19.56,26.16 16,26.16 14.48,24.64 8.76,24.64 8.76,19.56 8.76,9.53 7.62,8.38 v7.62,6.6
VDD1.8  (via drill 0.3)
  Top 0.356: C12.2 29.97,20.32 29.97,19.35 | 29.97,19.35 IC3.5 | v29.97,23.88 29.97,19.35 | R1!.1 15.75,6.86 v15.75,7.62
  Bottom 0.356: v29.97,23.88 29.72,24.13 24,24.13 23.11,23.24 23.11,22.23 19.94,19.05 19.94,10.67 18.54,9.27 17.02,9.27 15.75,8 v15.75,7.62
VDD1.8_OUT  (via drill 0.3)
  Top 0.356: IC1.7 9.02,25.27 8.64,24.89 | 8.64,24.89 6.6,24.89 6.35,24.89 6.1,25.15 C4.2 | v10.16,23.37 8.64,24.89 | C2.+ 8.89,4.06 v8.89,5.59 9.65,6.35 10.16,6.35 | 10.16,6.35 R1!.2 | 10.16,6.35 TP1.TP
  Bottom 0.356: v10.16,23.37 10.16,21.34 R1.2 10.25,20.66 9.65,20.07 9.65,8.89 8.89,8.13 v8.89,5.59
VDD3.3  (via drill 0.3)
  Top 0.356: C11.2 40.13,18.03 40.12,18.03 IC3.40 v37.08,14.99 | 28.19,7.62 C10.2 | 28.19,7.62 28.19,8.94 IC3.17 32.13,12.87 v32.13,14.16 | 28.19,7.62 27.94,7.37 27.69,7.37 24.64,7.37 24.13,6.86 24.13,5.59 24.13,5.08 | 24.13,5.08 25.91,5.08 26.67,4.32 26.67,3.68 27.18,3.17 27.3,3.17 IC2.6 29.59,3.17 29.72,3.17 30.48,2.41 30.48,1.65 30.73,1.4 v30.99,1.4 | v51.05,4.57 v51.05,8.89 | v36.8,0.51 36.8,2.79 38.1,4.32 40.64,4.32 44.45,0.51 53.34,0.51 54.1,1.27 v54.1,3.3 | 19.05,5.08 17.78,5.08 16.61,3.92 C22.+ 13.72,3.81 v16.51,3.81 | 19.05,5.08 24.13,5.08 | v16.51,11.43 16.51,10.67 18.03,9.14 20.57,9.14 21.08,8.64 21.08,8.13 20.83,7.87 | 19.05,5.08 19.05,7.11 v19.56,7.62 20.57,7.62 20.83,7.87 | 20.83,7.87 v21.08,7.87
  Bottom 0.356: v32.13,14.16 32.96,14.99 v37.08,14.99 | R8.1 49.36,2.88 v51.05,4.57 52.83,4.57 v54.1,3.3 | v51.05,8.89 50.55,8.89 49.78,9.65 49.78,13.72 51.56,15.49 51.56,18.03 51.05,18.54 50.04,18.54 49.95,18.63 R7.1 | v36.8,0.51 35.94,1.4 v30.99,1.4 30.99,1.27 30.73,1.02 C6.2 | 17.44,20.66 R2!.1 | 17.44,20.66 17.4,20.57 17.4,12.57 16.51,11.68 v16.51,11.43 16.42,11.26 R5.2 | v16.51,3.81 R10.2 | D2.1 19.49,7.55 v19.56,7.62 | R4.2 23.62,20.32 21.21,17.91 21.21,8 v21.08,7.87 | 17.44,20.66 17.61,20.66 18.8,21.84 18.8,22.86 18.88,22.78 D1.2
VDDA  (via drill 0.3)
  Top 0.356: 35.56,22.35 C17.2 35.56,21.84 35.81,22.1 v37.08,22.1 37.34,21.84 38.1,21.84 38.61,21.34 38.61,19.3 | IC3.42 38.61,17.93 38.61,19.3 | C16.+ 11.43,4.06 v11.43,5.59 | 38.61,19.3 TP4.TP
  Bottom 0.356: v37.08,22.1 36.58,22.1 34.04,24.64 23.62,24.64 22.61,23.62 22.61,22.61 19.3,19.3 19.3,10.92 19.05,10.67 18.29,9.91 16.76,9.91 12.95,6.1 12.95,5.59 | 12.95,5.59 12.95,4.32 12.95,3.81 R10.1 | v11.43,5.59 12.95,5.59
VDDIO  (via drill 0.3)
  Top 0.356: IC4.19 13.11,15.6 12.95,15.75 12.95,16.51 12.95,16.76 13.09,16.89 IC4.17 15.88,16.89 v16.26,17.27 16.26,18.29 15.26,19.29 C7.1 15.26,20.08 15.24,20.07 TP2.TP | IC4.4 19.55,11.7 18.29,12.95 16.5,12.96 v16.26,12.95
  Bottom 0.356: R2!.2 16.26,18.8 v16.26,17.27 16,17.27 15.49,16.76 15.49,13.46 16,12.95 v16.26,12.95
WP/  (via drill 0.3)
  Top 0.356: IC2.5 27.81,4.45 v26.99,5.21
  Bottom 0.356: R3!.1 52.28,1.14 49.4,1.14 49.31,1.14 R8.2 48.86,0.76 46.99,0.76 43.69,0.76 40.26,4.19 28.26,4.19 28.07,4.19 27.05,5.21 v26.99,5.21
(copper drawn outside any net)
  shapes: Bottom circle x2, Top circle x2

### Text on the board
Bottom: - | +
tNames: - | +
